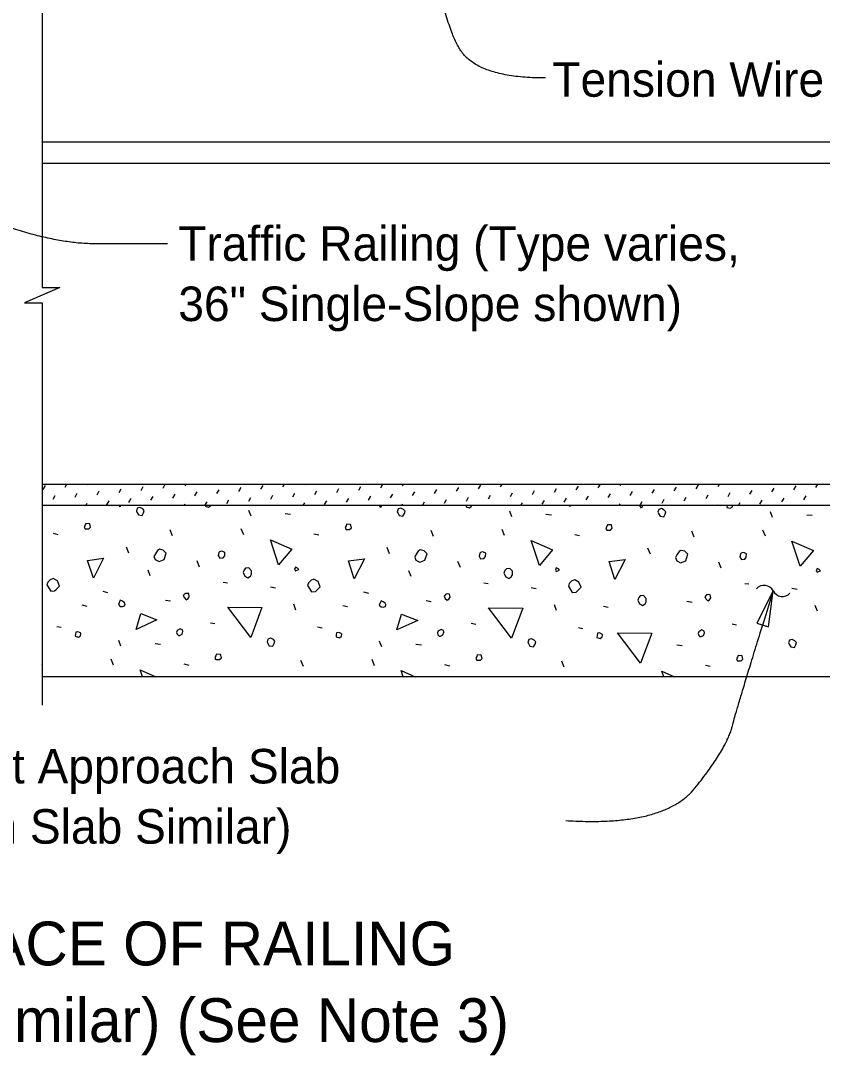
# Model space of a CAD drawing. Extents: x 0.2 to 40.8, y 0.5 to 25.7.
# Drawn here: x 16.13 to 20.81, y 10.89 to 16.93 of the extents above; entities that cross this region are included whole.
import ezdxf

# ---------------------------------------------------------------- set-up
doc = ezdxf.new("R2010")
doc.units = 0
for name, color, linetype in [('Dimension', 7, 'Continuous'), ('Miscellaneous', 7, 'Continuous'), ('SupstrConc', 7, 'Continuous'), ('TextStructures', 7, 'Continuous')]:
    doc.layers.add(name, color=color, linetype=linetype)

msp = doc.modelspace()

# ---------------------------------------------------------------- linework, layer by layer
at = {"layer": 'Dimension'}
msp.add_lwpolyline([(16.252, 17.2246), (16.252, 15.3737), (16.3553, 15.3737), (16.252, 15.3287), (16.1487, 15.2837), (16.252, 15.2837), (16.252, 12.9339)], dxfattribs=at)
msp.add_lwpolyline([(20.5246, 13.6005), (20.4289, 13.4122), (20.4962, 13.3912)], close=True, dxfattribs=at)
for centre, start, end in [((20.4706, 13.5736), 26.84133, 138.56855), ((20.577, 13.6275), 206.84133, 318.56855)]:
    msp.add_arc(centre, 0.0596, start, end, dxfattribs=at)
for points in [[(19.1927, 16.5972), (18.7949, 16.5972), (18.5909, 16.9342), (18.5297, 17.3911)], [(16.9853, 15.6282), (16.9154, 15.6282), (16.2159, 15.6282), (15.6583, 15.8852)], [(19.3131, 12.2588), (19.886, 12.2223), (20.2509, 12.679), (20.3172, 12.9363), (20.5245, 13.6004)]]:
    msp.add_open_spline(points, degree=2, dxfattribs=at)
at = {"layer": 'Miscellaneous'}
for p, q in [((16.2587, 14.1938), (16.2717, 14.2162)), ((16.3872, 14.2068), (16.3975, 14.2245)), ((16.5157, 14.2197), (16.5184, 14.2245)), ((16.8303, 14.1879), (16.8433, 14.2103)), ((16.9588, 14.2009), (16.9717, 14.2233)), ((17.0872, 14.2138), (17.0934, 14.2245)), ((17.5303, 14.195), (17.5433, 14.2174)), ((17.6588, 14.2079), (17.6684, 14.2245)), ((17.7873, 14.2209), (17.7893, 14.2245)), ((18.1019, 14.1891), (18.1149, 14.2115)), ((18.2304, 14.2021), (18.2433, 14.2244)), ((18.3588, 14.215), (18.3643, 14.2245)), ((18.6735, 14.1832), (18.6865, 14.2056)), ((18.802, 14.1962), (18.8149, 14.2186)), ((18.9304, 14.2091), (18.9393, 14.2245)), ((19.0589, 14.2221), (19.0603, 14.2245)), ((19.3735, 14.1903), (19.3865, 14.2127)), ((19.502, 14.2032), (19.5143, 14.2245)), ((19.6305, 14.2162), (19.6353, 14.2245)), ((19.9451, 14.1844), (19.9581, 14.2068)), ((20.0736, 14.1973), (20.0865, 14.2197)), ((20.202, 14.2103), (20.2103, 14.2245)), ((20.3305, 14.2233), (20.3312, 14.2245)), ((20.6452, 14.1914), (20.6581, 14.2138)), ((20.7736, 14.2044), (20.7852, 14.2245)), ((16.3165, 14.1361), (16.3294, 14.1584)), ((16.4449, 14.149), (16.4579, 14.1714)), ((16.5734, 14.162), (16.5864, 14.1844)), ((16.7019, 14.1749), (16.7148, 14.1973)), ((16.8881, 14.1302), (16.901, 14.1526)), ((17.0165, 14.1431), (17.0295, 14.1655)), ((17.145, 14.1561), (17.1579, 14.1785)), ((17.2734, 14.1691), (17.2864, 14.1914)), ((17.4019, 14.182), (17.4149, 14.2044)), ((17.4596, 14.1243), (17.4726, 14.1467)), ((17.5881, 14.1372), (17.6011, 14.1596)), ((17.7166, 14.1502), (17.7295, 14.1726)), ((17.845, 14.1632), (17.858, 14.1856)), ((17.9735, 14.1761), (17.9864, 14.1985)), ((18.1597, 14.1313), (18.1726, 14.1537)), ((18.2881, 14.1443), (18.3011, 14.1667)), ((18.4166, 14.1573), (18.4296, 14.1797)), ((18.545, 14.1702), (18.558, 14.1926)), ((18.7313, 14.1254), (18.7442, 14.1478)), ((18.8597, 14.1384), (18.8727, 14.1608)), ((18.9882, 14.1514), (19.0011, 14.1738)), ((19.1166, 14.1643), (19.1296, 14.1867)), ((19.2451, 14.1773), (19.258, 14.1997)), ((19.4313, 14.1325), (19.4443, 14.1549)), ((19.5597, 14.1455), (19.5727, 14.1679)), ((19.6882, 14.1584), (19.7012, 14.1808)), ((19.8167, 14.1714), (19.8296, 14.1938)), ((20.0029, 14.1266), (20.0158, 14.149)), ((20.1313, 14.1396), (20.1443, 14.162)), ((20.2598, 14.1526), (20.2727, 14.1749)), ((20.3882, 14.1655), (20.4012, 14.1879)), ((20.5167, 14.1785), (20.5297, 14.2009)), ((20.7029, 14.1337), (20.7159, 14.1561)), ((16.5075, 14.0995), (16.5157, 14.1137)), ((16.6311, 14.1042), (16.6441, 14.1266)), ((16.7596, 14.1172), (16.7726, 14.1396)), ((17.0825, 14.0995), (17.0872, 14.1078)), ((17.2034, 14.0995), (17.2157, 14.1207)), ((17.3312, 14.1113), (17.3441, 14.1337)), ((17.6574, 14.0995), (17.6588, 14.1019)), ((17.7784, 14.0995), (17.7873, 14.1148)), ((17.9028, 14.1054), (17.9157, 14.1278)), ((18.0312, 14.1184), (18.0442, 14.1408)), ((18.3534, 14.0995), (18.3588, 14.1089)), ((18.4743, 14.0995), (18.4873, 14.1219)), ((18.6028, 14.1125), (18.6158, 14.1349)), ((19.0493, 14.0995), (19.0589, 14.116)), ((19.1744, 14.1066), (19.1873, 14.129)), ((19.3028, 14.1196), (19.3158, 14.1419)), ((19.6243, 14.0995), (19.6305, 14.1101)), ((19.746, 14.1007), (19.7589, 14.1231)), ((19.8744, 14.1137), (19.8874, 14.1361)), ((20.1993, 14.0995), (20.202, 14.1042)), ((20.3203, 14.0995), (20.3305, 14.1172)), ((20.446, 14.1078), (20.459, 14.1302)), ((20.5744, 14.1207), (20.5874, 14.1431)), ((17.4727, 14.0371), (17.4603, 14.0707)), ((17.6725, 14.053), (17.7043, 14.0495)), ((18.9965, 14.0336), (18.9841, 14.0672)), ((19.1963, 14.0495), (19.2281, 14.046)), ((20.5203, 14.03), (20.508, 14.0636)), ((20.7201, 14.046), (20.7519, 14.0424)), ((17.4303, 13.9275), (17.4161, 13.9629)), ((16.3166, 13.9381), (16.3449, 13.931)), ((17.0148, 13.9222), (17.0007, 13.9576)), ((17.8404, 13.9346), (17.8687, 13.9275)), ((18.5387, 13.9187), (18.5245, 13.954)), ((18.9541, 13.924), (18.9399, 13.9593)), ((19.3642, 13.931), (19.3925, 13.924)), ((20.0625, 13.9151), (20.0483, 13.9505)), ((20.4779, 13.9204), (20.4638, 13.9558)), ((16.7585, 13.8214), (16.7444, 13.8568)), ((18.2823, 13.8179), (18.2682, 13.8533)), ((19.8062, 13.8144), (19.792, 13.8497)), ((16.884, 13.6889), (16.8717, 13.7225)), ((17.1722, 13.7401), (17.158, 13.7755)), ((18.696, 13.7366), (18.6819, 13.7719)), ((20.2198, 13.7331), (20.2057, 13.7684)), ((18.4078, 13.6853), (18.3955, 13.7189)), ((17.3101, 13.6517), (17.3348, 13.6482)), ((17.5858, 13.6235), (17.6159, 13.6182)), ((18.8339, 13.6482), (18.8586, 13.6447)), ((19.1097, 13.6199), (19.1397, 13.6146)), ((20.3577, 13.6447), (20.3824, 13.6411)), ((20.6335, 13.6164), (20.6635, 13.6111)), ((16.6065, 13.5987), (16.6348, 13.5916)), ((16.9724, 13.5474), (17.0025, 13.5421)), ((18.1303, 13.5952), (18.1586, 13.5881)), ((18.4962, 13.5439), (18.5263, 13.5386)), ((20.0201, 13.5404), (20.0501, 13.5351)), ((16.4845, 13.5192), (16.5128, 13.5121)), ((17.7343, 13.4891), (17.722, 13.5227)), ((18.0083, 13.5156), (18.0366, 13.5086)), ((19.2581, 13.4856), (19.2458, 13.5192)), ((19.5321, 13.5121), (19.5604, 13.505)), ((20.782, 13.482), (20.7696, 13.5156)), ((16.3378, 13.3936), (16.3643, 13.3883)), ((17.2358, 13.4149), (17.2623, 13.4096)), ((17.8616, 13.3901), (17.8881, 13.3848)), ((18.7596, 13.4113), (18.7862, 13.406)), ((19.3854, 13.3866), (19.4119, 13.3813)), ((20.2834, 13.4078), (20.31, 13.4025)), ((16.7126, 13.277), (16.7002, 13.3106)), ((18.2364, 13.2734), (18.224, 13.307)), ((16.9123, 13.2929), (16.9441, 13.2893)), ((18.4361, 13.2893), (18.468, 13.2858)), ((19.9599, 13.2858), (19.9918, 13.2823)), ((16.6701, 13.1674), (16.656, 13.2027)), ((17.7785, 13.1585), (17.7644, 13.1939)), ((18.1939, 13.1638), (18.1798, 13.1992)), ((19.3023, 13.155), (19.2882, 13.1904)), ((16.2547, 13.1621), (16.252, 13.1689)), ((17.0803, 13.1744), (17.1085, 13.1674)), ((18.6041, 13.1709), (18.6324, 13.1638)), ((20.1279, 13.1674), (20.1562, 13.1603))]:
    msp.add_line(p, q, dxfattribs=at)
for points in [[(16.7073, 14.0919), (16.7015, 14.0995)], [(16.7101, 14.0995), (16.7073, 14.0919)], [(16.8063, 14.0601), (16.8151, 14.0442), (16.8363, 14.0406), (16.8451, 14.0566), (16.8487, 14.0707), (16.8398, 14.0795), (16.8239, 14.0884), (16.808, 14.0831), (16.8027, 14.0672), (16.8063, 14.0601)], [(17.2058, 14.0954), (17.2252, 14.0901), (17.2376, 14.099), (17.2377, 14.0995)], [(17.2063, 14.0995), (17.2058, 14.0954)], [(18.2311, 14.0884), (18.2226, 14.0995)], [(18.2352, 14.0995), (18.2311, 14.0884)], [(18.3301, 14.0566), (18.3389, 14.0406), (18.3601, 14.0371), (18.369, 14.053), (18.3725, 14.0672), (18.3637, 14.076), (18.3477, 14.0848), (18.3318, 14.0795), (18.3265, 14.0636), (18.3301, 14.0566)], [(18.7296, 14.0919), (18.749, 14.0866), (18.7614, 14.0954), (18.762, 14.0995)], [(18.7307, 14.0995), (18.7296, 14.0919)], [(19.3301, 14.0995), (19.3324, 14.0972)], [(19.3324, 14.0972), (19.3395, 14.0972), (19.3441, 14.0995)], [(19.7549, 14.0848), (19.7437, 14.0995)], [(19.7604, 14.0995), (19.7549, 14.0848)], [(20.2534, 14.0884), (20.2728, 14.0831), (20.2852, 14.0919), (20.2863, 14.0995)], [(20.255, 14.0995), (20.2534, 14.0884)], [(19.8539, 14.053), (19.8627, 14.0371), (19.8839, 14.0336), (19.8928, 14.0495), (19.8963, 14.0636), (19.8875, 14.0725), (19.8716, 14.0813), (19.8556, 14.076), (19.8503, 14.0601), (19.8539, 14.053)], [(16.504, 13.9629), (16.5252, 13.9629), (16.5358, 13.9735), (16.5305, 13.9929), (16.5075, 13.9947), (16.504, 13.9841), (16.4987, 13.9752), (16.504, 13.9629), (16.5004, 13.9664)], [(18.0278, 13.9593), (18.049, 13.9593), (18.0596, 13.9699), (18.0543, 13.9894), (18.0313, 13.9912), (18.0278, 13.9805), (18.0225, 13.9717), (18.0278, 13.9593), (18.0242, 13.9629)], [(19.5516, 13.9558), (19.5728, 13.9558), (19.5834, 13.9664), (19.5781, 13.9858), (19.5551, 13.9876), (19.5516, 13.977), (19.5463, 13.9682), (19.5516, 13.9558), (19.5481, 13.9593)], [(16.9123, 13.7843), (16.9353, 13.7719), (16.9654, 13.7843), (16.9777, 13.8214), (16.96, 13.8391), (16.9371, 13.8444), (16.9265, 13.8374), (16.9141, 13.8179), (16.9052, 13.802), (16.9123, 13.7843)], [(17.6336, 13.7525), (17.5858, 13.8992), (17.7113, 13.8444), (17.6336, 13.7525)], [(19.1574, 13.749), (19.1097, 13.8957), (19.2352, 13.8409), (19.1574, 13.749)], [(20.6812, 13.7454), (20.6335, 13.8922), (20.759, 13.8374), (20.6812, 13.7454)], [(16.5517, 13.6747), (16.5181, 13.779), (16.6118, 13.7914), (16.5517, 13.6747)], [(17.2818, 13.8073), (17.2906, 13.7914), (17.3101, 13.7932), (17.3189, 13.8055), (17.3207, 13.825), (17.3083, 13.8303), (17.2995, 13.8321), (17.2889, 13.8285), (17.2853, 13.825), (17.2818, 13.8073)], [(18.0755, 13.6712), (18.0419, 13.7755), (18.1356, 13.7879), (18.0755, 13.6712)], [(18.4361, 13.7808), (18.4591, 13.7684), (18.4892, 13.7808), (18.5015, 13.8179), (18.4839, 13.8356), (18.4609, 13.8409), (18.4503, 13.8338), (18.4379, 13.8144), (18.4291, 13.7985), (18.4361, 13.7808)], [(18.8056, 13.8038), (18.8144, 13.7879), (18.8339, 13.7896), (18.8427, 13.802), (18.8445, 13.8214), (18.8321, 13.8267), (18.8233, 13.8285), (18.8127, 13.825), (18.8091, 13.8214), (18.8056, 13.8038)], [(19.5993, 13.6677), (19.5657, 13.7719), (19.6594, 13.7843), (19.5993, 13.6677)], [(19.9599, 13.7773), (19.9829, 13.7649), (20.013, 13.7773), (20.0254, 13.8144), (20.0077, 13.8321), (19.9847, 13.8374), (19.9741, 13.8303), (19.9617, 13.8108), (19.9529, 13.7949), (19.9599, 13.7773)], [(20.3294, 13.8002), (20.3382, 13.7843), (20.3577, 13.7861), (20.3665, 13.7985), (20.3683, 13.8179), (20.3559, 13.8232), (20.3471, 13.825), (20.3365, 13.8214), (20.3329, 13.8179), (20.3294, 13.8002)], [(17.4267, 13.7083), (17.4373, 13.6871), (17.455, 13.6765), (17.4692, 13.6871), (17.4762, 13.6977), (17.4762, 13.7189), (17.4603, 13.7348), (17.4409, 13.7331), (17.432, 13.7242), (17.4267, 13.7083)], [(17.7326, 13.7171), (17.752, 13.726), (17.7449, 13.7331), (17.7326, 13.7384), (17.7273, 13.726), (17.7326, 13.7171)], [(18.9506, 13.7048), (18.9612, 13.6836), (18.9788, 13.673), (18.993, 13.6836), (19.0001, 13.6942), (19.0001, 13.7154), (18.9841, 13.7313), (18.9647, 13.7295), (18.9559, 13.7207), (18.9506, 13.7048)], [(19.2564, 13.7136), (19.2758, 13.7225), (19.2688, 13.7295), (19.2564, 13.7348), (19.2511, 13.7225), (19.2564, 13.7136)], [(20.7802, 13.7101), (20.7996, 13.7189), (20.7926, 13.726), (20.7802, 13.7313), (20.7749, 13.7189), (20.7802, 13.7101)], [(16.2795, 13.6358), (16.3024, 13.5987), (16.3254, 13.6005), (16.3343, 13.6093), (16.3537, 13.6288), (16.3413, 13.6588), (16.3166, 13.673), (16.2989, 13.6659), (16.2848, 13.6517), (16.2795, 13.6358)], [(17.8033, 13.6323), (17.8263, 13.5952), (17.8492, 13.5969), (17.8581, 13.6058), (17.8775, 13.6252), (17.8651, 13.6553), (17.8404, 13.6694), (17.8227, 13.6623), (17.8086, 13.6482), (17.8033, 13.6323)], [(19.3271, 13.6288), (19.3501, 13.5916), (19.373, 13.5934), (19.3819, 13.6022), (19.4013, 13.6217), (19.389, 13.6517), (19.3642, 13.6659), (19.3465, 13.6588), (19.3324, 13.6447), (19.3271, 13.6288)], [(16.709, 13.5103), (16.7214, 13.5086), (16.7338, 13.5139), (16.7373, 13.5245), (16.732, 13.5333), (16.7214, 13.5404), (16.709, 13.5457), (16.702, 13.5315), (16.6984, 13.5209), (16.709, 13.5103)], [(17.0838, 13.5598), (17.0944, 13.5492), (17.105, 13.5563), (17.1121, 13.5669), (17.1085, 13.5846), (17.0997, 13.5863), (17.0873, 13.5846), (17.0767, 13.574), (17.0838, 13.5598)], [(18.2328, 13.5068), (18.2452, 13.505), (18.2576, 13.5103), (18.2611, 13.5209), (18.2558, 13.5298), (18.2452, 13.5368), (18.2328, 13.5421), (18.2258, 13.528), (18.2222, 13.5174), (18.2328, 13.5068)], [(18.6076, 13.5563), (18.6182, 13.5457), (18.6288, 13.5527), (18.6359, 13.5634), (18.6324, 13.581), (18.6235, 13.5828), (18.6111, 13.581), (18.6005, 13.5704), (18.6076, 13.5563)], [(19.7325, 13.5466), (19.7431, 13.5254), (19.7608, 13.5148), (19.7749, 13.5254), (19.782, 13.536), (19.782, 13.5572), (19.7661, 13.5731), (19.7467, 13.5713), (19.7378, 13.5625), (19.7325, 13.5466)], [(20.1314, 13.5527), (20.142, 13.5421), (20.1526, 13.5492), (20.1597, 13.5598), (20.1562, 13.5775), (20.1473, 13.5793), (20.135, 13.5775), (20.1244, 13.5669), (20.1314, 13.5527)], [(17.4709, 13.3282), (17.3366, 13.505), (17.5363, 13.5032), (17.4709, 13.3282)], [(18.9947, 13.3247), (18.8604, 13.5015), (19.0602, 13.4997), (18.9947, 13.3247)], [(16.8009, 13.376), (16.8292, 13.4679), (16.9229, 13.4308), (16.8009, 13.376)], [(18.3248, 13.3724), (18.353, 13.4644), (18.4467, 13.4272), (18.3248, 13.3724)], [(16.4456, 13.3353), (16.4651, 13.33), (16.4774, 13.3388), (16.4792, 13.3512), (16.4757, 13.3548), (16.4615, 13.3618), (16.4492, 13.3601), (16.4474, 13.3477), (16.4456, 13.3353)], [(17.0484, 13.3406), (17.0555, 13.3406), (17.0696, 13.3477), (17.075, 13.3636), (17.0732, 13.3724), (17.059, 13.3795), (17.0414, 13.3689), (17.0378, 13.3583), (17.0414, 13.3477), (17.0484, 13.3406)], [(17.9694, 13.3318), (17.9889, 13.3265), (18.0013, 13.3353), (18.003, 13.3477), (17.9995, 13.3512), (17.9854, 13.3583), (17.973, 13.3565), (17.9712, 13.3441), (17.9694, 13.3318)], [(18.5723, 13.3371), (18.5793, 13.3371), (18.5935, 13.3441), (18.5988, 13.3601), (18.597, 13.3689), (18.5829, 13.376), (18.5652, 13.3654), (18.5616, 13.3548), (18.5652, 13.3441), (18.5723, 13.3371)], [(20.0961, 13.3335), (20.1031, 13.3335), (20.1173, 13.3406), (20.1226, 13.3565), (20.1208, 13.3654), (20.1067, 13.3724), (20.089, 13.3618), (20.0855, 13.3512), (20.089, 13.3406), (20.0961, 13.3335)], [(17.5699, 13.2964), (17.5788, 13.2805), (17.6, 13.277), (17.6088, 13.2929), (17.6124, 13.307), (17.6035, 13.3159), (17.5876, 13.3247), (17.5717, 13.3194), (17.5664, 13.3035), (17.5699, 13.2964)], [(19.0937, 13.2929), (19.1026, 13.277), (19.1238, 13.2734), (19.1326, 13.2893), (19.1362, 13.3035), (19.1273, 13.3123), (19.1114, 13.3212), (19.0955, 13.3159), (19.0902, 13.3), (19.0937, 13.2929)], [(19.4933, 13.3282), (19.5127, 13.3229), (19.5251, 13.3318), (19.5268, 13.3441), (19.5233, 13.3477), (19.5092, 13.3548), (19.4968, 13.353), (19.495, 13.3406), (19.4933, 13.3282)], [(19.7486, 13.1794), (19.6143, 13.3562), (19.814, 13.3544), (19.7486, 13.1794)], [(20.6176, 13.2893), (20.6264, 13.2734), (20.6476, 13.2699), (20.6564, 13.2858), (20.66, 13.3), (20.6511, 13.3088), (20.6352, 13.3176), (20.6193, 13.3123), (20.614, 13.2964), (20.6176, 13.2893)], [(17.2676, 13.1992), (17.2889, 13.1992), (17.2995, 13.2098), (17.2942, 13.2292), (17.2712, 13.231), (17.2676, 13.2204), (17.2623, 13.2116), (17.2676, 13.1992), (17.2641, 13.2027)], [(18.7915, 13.1957), (18.8127, 13.1957), (18.8233, 13.2063), (18.818, 13.2257), (18.795, 13.2275), (18.7915, 13.2169), (18.7862, 13.208), (18.7915, 13.1957), (18.7879, 13.1992)], [(20.3153, 13.1921), (20.3365, 13.1921), (20.3471, 13.2027), (20.3418, 13.2222), (20.3188, 13.2239), (20.3153, 13.2133), (20.31, 13.2045), (20.3153, 13.1921), (20.3117, 13.1957)], [(16.8386, 13.0995), (16.8257, 13.1391), (16.9163, 13.0995)], [(18.3612, 13.0995), (18.3495, 13.1356), (18.432, 13.0995)], [(19.8839, 13.0995), (19.8733, 13.132), (19.9477, 13.0995)]]:
    msp.add_lwpolyline(points, dxfattribs=at)
at = {"layer": 'SupstrConc'}
for p, q in [((16.252, 16.2245), (23.5538, 16.2245)), ((16.252, 16.0995), (23.5538, 16.0995)), ((16.252, 14.2245), (23.5538, 14.2245)), ((21.5538, 14.0995), (16.252, 14.0995)), ((21.9365, 13.0995), (16.252, 13.0995))]:
    msp.add_line(p, q, dxfattribs=at)

# ---------------------------------------------------------------- texts
at = {"layer": 'Dimension'}
for s, height, p in [('Traffic Railing (Type varies,', 0.2016, (17.0479, 15.5291)), ('36" Single-Slope shown)', 0.2016, (17.0479, 15.1771)), ('Approach Slab (Flexible Pavement Approach Slab ', 0.2016, (11.9999, 12.4759)), ('Shown, Rigid Pavement Approach Slab Similar)', 0.2016, (11.9999, 12.1239)), ('ELEVATION OF OUTSIDE FACE OF RAILING', 0.256001, (11.5134, 11.4128)), ('(Traffic Railing Shown, Concrete Parapet Similar) (See Note 3)', 0.256001, (9.4668, 10.9648))]:
    msp.add_text(s, height=height, dxfattribs=at).set_placement(p)
at = {"layer": 'TextStructures'}
msp.add_text('Tension Wire', height=0.2016, dxfattribs=at).set_placement((19.2335, 16.4877))

doc.saveas('drawing.dxf')
